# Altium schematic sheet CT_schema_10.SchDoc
size 274 x 160 mm
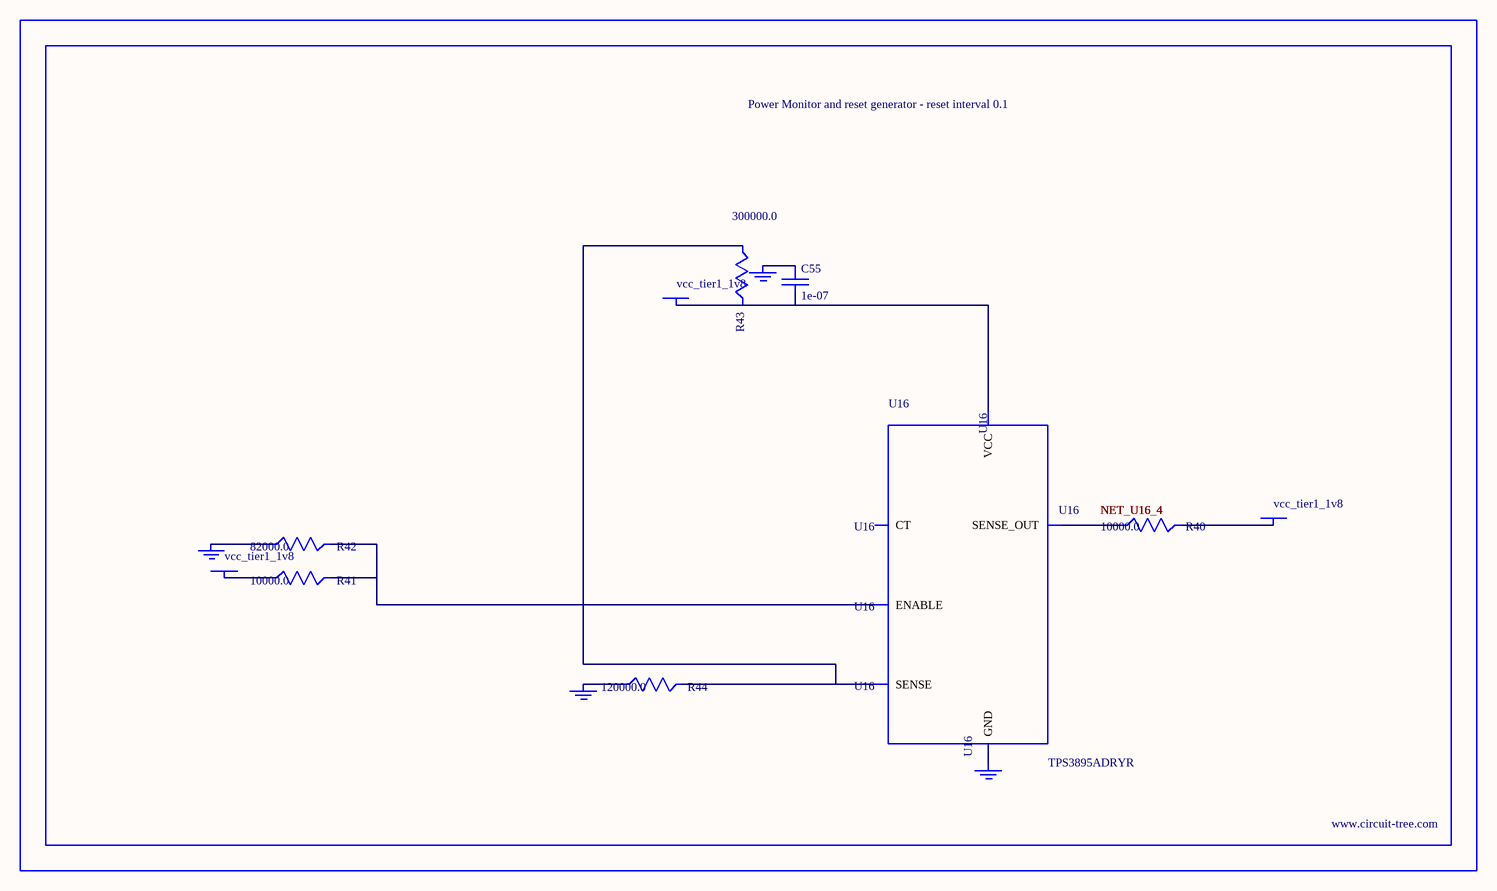
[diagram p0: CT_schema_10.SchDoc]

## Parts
BORDER9  (no value)
C55  1e-07  [C0402]
GND_INSTANCE_9_0  (no value)
GND_INSTANCE_9_1  (no value)
GND_INSTANCE_9_2  (no value)
GND_INSTANCE_9_3  (no value)
POWER_INSTANCE_9_0  vcc_tier1_1v8
POWER_INSTANCE_9_1  vcc_tier1_1v8
POWER_INSTANCE_9_2  vcc_tier1_1v8
R40  10000.0  [R0603]
R41  10000.0  [R0603]
R42  82000.0  [R0603]
R43  300000.0  [R0603]
R44  120000.0  [R0603]
U16  TPS3895ADRYR  [SON-6]

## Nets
NetC55_1: C55.1 GND_INSTANCE_9_2.0(GND)
NetC55_2: C55.2 POWER_INSTANCE_9_2.0(PWR) R43.2 U16.6(VCC)
NetGND_INSTANCE_9_0_0: GND_INSTANCE_9_0.0(GND) R42.1
NetGND_INSTANCE_9_1_0: GND_INSTANCE_9_1.0(GND) R44.1
NetGND_INSTANCE_9_3_0: GND_INSTANCE_9_3.0(GND) U16.2(GND)
NetPOWER_INSTANCE_9_0_0: POWER_INSTANCE_9_0.0(PWR) R41.1
NetPOWER_INSTANCE_9_1_0: POWER_INSTANCE_9_1.0(PWR) R40.2
NetR40_1: R40.1 U16.4(SENSE_OUT)
NetR41_2: R41.2 R42.2 U16.1(ENABLE)
NetR43_1: R43.1 R44.2 U16.3(SENSE)

Not connected (* = marked no-connect by the designer): U16 5(CT)

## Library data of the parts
BORDER9 = BORDER_PAGE9
C55 = C0402C104K3RACTU
GND_INSTANCE_9_0-GND_INSTANCE_9_3 = GND
POWER_INSTANCE_9_0-POWER_INSTANCE_9_2 = PWR
R40 R41 = RC0603JR-0710KL
R42 = RC0603JR-0782KL
R43 = RC0603JR-07300KL
R44 = RC0603JR-07120KL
